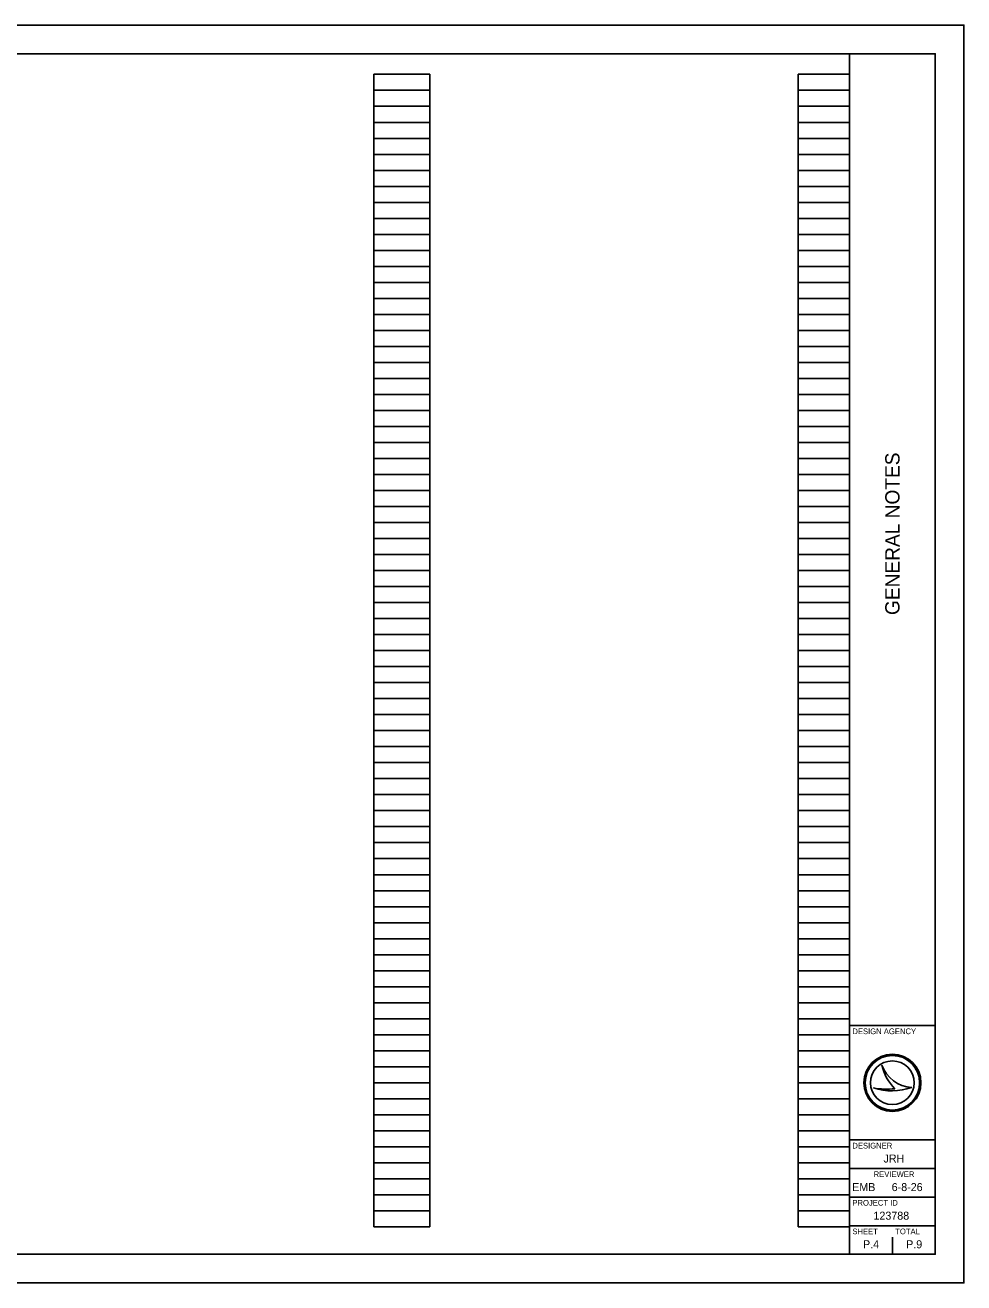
# Model space of a CAD drawing. Extents: x 0 to 34, y 0 to 22.
# Drawn here: x 17.58 to 34, y 0 to 22 of the extents above; entities that cross this region are included whole.
import ezdxf

# ---------------------------------------------------------------- set-up
doc = ezdxf.new("R2010")
doc.units = 0
for name, color, linetype in [('SH_Border', 7, 'Continuous'), ('SH_Cut_Line', 7, 'Continuous'), ('SH_Data', 7, 'Continuous')]:
    doc.layers.add(name, color=color, linetype=linetype)

msp = doc.modelspace()

# ---------------------------------------------------------------- linework, layer by layer
at = {"layer": 'SH_Border'}
for p, q in [((32, 0.5), (32, 21.5)), ((32, 4.5), (33.5, 4.5)), ((32, 2.5), (33.5, 2.5)), ((32, 2), (33.5, 2)), ((32, 1.5), (33.5, 1.5)), ((32, 1), (33.5, 1))]:
    msp.add_line(p, q, dxfattribs=at)
msp.add_lwpolyline([(1.5, 21.5), (33.5, 21.5), (33.5, 0.5), (1.5, 0.5)], close=True, dxfattribs=at)
at = {"layer": 'SH_Cut_Line'}
msp.add_lwpolyline([(0, 0), (34, 0), (34, 22), (0, 22)], close=True, dxfattribs=at)
at = {"layer": 'SH_Data'}
for p, q in [((23.68, 0.98), (23.68, 21.14)), ((23.68, 21.14), (24.66, 21.14)), ((24.66, 0.98), (24.66, 21.14)), ((31.1, 0.98), (31.1, 21.14)), ((31.1, 21.14), (32, 21.14)), ((32, 0.98), (32, 21.14)), ((23.68, 20.86), (24.66, 20.86)), ((31.1, 20.86), (32, 20.86)), ((23.68, 20.58), (24.66, 20.58)), ((31.1, 20.58), (32, 20.58)), ((23.68, 20.3), (24.66, 20.3)), ((31.1, 20.3), (32, 20.3)), ((23.68, 20.02), (24.66, 20.02)), ((31.1, 20.02), (32, 20.02)), ((23.68, 19.74), (24.66, 19.74)), ((31.1, 19.74), (32, 19.74)), ((23.68, 19.46), (24.66, 19.46)), ((31.1, 19.46), (32, 19.46)), ((23.68, 19.18), (24.66, 19.18)), ((31.1, 19.18), (32, 19.18)), ((23.68, 18.9), (24.66, 18.9)), ((31.1, 18.9), (32, 18.9)), ((23.68, 18.62), (24.66, 18.62)), ((31.1, 18.62), (32, 18.62)), ((23.68, 18.34), (24.66, 18.34)), ((31.1, 18.34), (32, 18.34)), ((23.68, 18.06), (24.66, 18.06)), ((31.1, 18.06), (32, 18.06)), ((23.68, 17.78), (24.66, 17.78)), ((31.1, 17.78), (32, 17.78)), ((23.68, 17.5), (24.66, 17.5)), ((31.1, 17.5), (32, 17.5)), ((23.68, 17.22), (24.66, 17.22)), ((31.1, 17.22), (32, 17.22)), ((23.68, 16.94), (24.66, 16.94)), ((31.1, 16.94), (32, 16.94)), ((23.68, 16.66), (24.66, 16.66)), ((31.1, 16.66), (32, 16.66)), ((23.68, 16.38), (24.66, 16.38)), ((31.1, 16.38), (32, 16.38)), ((23.68, 16.1), (24.66, 16.1)), ((31.1, 16.1), (32, 16.1)), ((23.68, 15.82), (24.66, 15.82)), ((31.1, 15.82), (32, 15.82)), ((23.68, 15.54), (24.66, 15.54)), ((31.1, 15.54), (32, 15.54)), ((23.68, 15.26), (24.66, 15.26)), ((31.1, 15.26), (32, 15.26)), ((23.68, 14.98), (24.66, 14.98)), ((31.1, 14.98), (32, 14.98)), ((23.68, 14.7), (24.66, 14.7)), ((31.1, 14.7), (32, 14.7)), ((23.68, 14.42), (24.66, 14.42)), ((31.1, 14.42), (32, 14.42)), ((23.68, 14.14), (24.66, 14.14)), ((31.1, 14.14), (32, 14.14)), ((23.68, 13.86), (24.66, 13.86)), ((31.1, 13.86), (32, 13.86)), ((23.68, 13.58), (24.66, 13.58)), ((31.1, 13.58), (32, 13.58)), ((23.68, 13.3), (24.66, 13.3)), ((31.1, 13.3), (32, 13.3)), ((23.68, 13.02), (24.66, 13.02)), ((31.1, 13.02), (32, 13.02)), ((23.68, 12.74), (24.66, 12.74)), ((31.1, 12.74), (32, 12.74)), ((23.68, 12.46), (24.66, 12.46)), ((31.1, 12.46), (32, 12.46)), ((23.68, 12.18), (24.66, 12.18)), ((31.1, 12.18), (32, 12.18)), ((23.68, 11.9), (24.66, 11.9)), ((31.1, 11.9), (32, 11.9)), ((23.68, 11.62), (24.66, 11.62)), ((31.1, 11.62), (32, 11.62)), ((23.68, 11.34), (24.66, 11.34)), ((31.1, 11.34), (32, 11.34)), ((23.68, 11.06), (24.66, 11.06)), ((31.1, 11.06), (32, 11.06)), ((23.68, 10.78), (24.66, 10.78)), ((31.1, 10.78), (32, 10.78)), ((23.68, 10.5), (24.66, 10.5)), ((31.1, 10.5), (32, 10.5)), ((23.68, 10.22), (24.66, 10.22)), ((31.1, 10.22), (32, 10.22)), ((23.68, 9.94), (24.66, 9.94)), ((31.1, 9.94), (32, 9.94)), ((23.68, 9.66), (24.66, 9.66)), ((31.1, 9.66), (32, 9.66)), ((23.68, 9.38), (24.66, 9.38)), ((31.1, 9.38), (32, 9.38)), ((23.68, 9.1), (24.66, 9.1)), ((31.1, 9.1), (32, 9.1)), ((23.68, 8.82), (24.66, 8.82)), ((31.1, 8.82), (32, 8.82)), ((23.68, 8.54), (24.66, 8.54)), ((31.1, 8.54), (32, 8.54)), ((23.68, 8.26), (24.66, 8.26)), ((31.1, 8.26), (32, 8.26)), ((23.68, 7.98), (24.66, 7.98)), ((31.1, 7.98), (32, 7.98)), ((23.68, 7.7), (24.66, 7.7)), ((31.1, 7.7), (32, 7.7)), ((23.68, 7.42), (24.66, 7.42)), ((31.1, 7.42), (32, 7.42)), ((23.68, 7.14), (24.66, 7.14)), ((31.1, 7.14), (32, 7.14)), ((23.68, 6.86), (24.66, 6.86)), ((31.1, 6.86), (32, 6.86)), ((23.68, 6.58), (24.66, 6.58)), ((31.1, 6.58), (32, 6.58)), ((23.68, 6.3), (24.66, 6.3)), ((31.1, 6.3), (32, 6.3)), ((23.68, 6.02), (24.66, 6.02)), ((31.1, 6.02), (32, 6.02)), ((23.68, 5.74), (24.66, 5.74)), ((31.1, 5.74), (32, 5.74)), ((23.68, 5.46), (24.66, 5.46)), ((31.1, 5.46), (32, 5.46)), ((23.68, 5.18), (24.66, 5.18)), ((31.1, 5.18), (32, 5.18)), ((23.68, 4.9), (24.66, 4.9)), ((31.1, 4.9), (32, 4.9)), ((23.68, 4.62), (24.66, 4.62)), ((31.1, 4.62), (32, 4.62)), ((23.68, 4.34), (24.66, 4.34)), ((31.1, 4.34), (32, 4.34)), ((23.68, 4.06), (24.66, 4.06)), ((31.1, 4.06), (32, 4.06)), ((23.68, 3.78), (24.66, 3.78)), ((31.1, 3.78), (32, 3.78)), ((32.567, 3.81), (32.567, 3.81)), ((23.68, 3.5), (24.66, 3.5)), ((31.1, 3.5), (32, 3.5)), ((32.417, 3.41), (32.417, 3.41)), ((32.75, 3.5), (32.75, 3.5)), ((33.087, 3.419), (33.087, 3.419)), ((23.68, 3.22), (24.66, 3.22)), ((31.1, 3.22), (32, 3.22)), ((23.68, 2.94), (24.66, 2.94)), ((31.1, 2.94), (32, 2.94)), ((23.68, 2.66), (24.66, 2.66)), ((31.1, 2.66), (32, 2.66)), ((23.68, 2.38), (24.66, 2.38)), ((31.1, 2.38), (32, 2.38)), ((23.68, 2.1), (24.66, 2.1)), ((31.1, 2.1), (32, 2.1)), ((23.68, 1.82), (24.66, 1.82)), ((31.1, 1.82), (32, 1.82)), ((23.68, 1.54), (24.66, 1.54)), ((31.1, 1.54), (32, 1.54)), ((23.68, 1.26), (24.66, 1.26)), ((31.1, 1.26), (32, 1.26)), ((23.68, 0.98), (24.66, 0.98)), ((31.1, 0.98), (32, 0.98)), ((32.375, 0.675), (32.375, 0.675)), ((32.75, 0.5), (32.75, 0.8))]:
    msp.add_line(p, q, dxfattribs=at)
for radius in [0.5, 0.477, 0.477, 0.382]:
    msp.add_circle((32.75, 3.5), radius, dxfattribs=at)
for centre, radius, start, end in [((33.116, 3.998), 0.58, 198.9257, 198.9319), ((33.347, 3.97), 0.796, 191.6379, 191.6421), ((33.116, 3.998), 0.58, 198.9319, 267.1657), ((33.347, 3.97), 0.796, 191.6421, 226.0947), ((32.739, 4.37), 1.013, 251.4576, 290.0832), ((32.648, 4.654), 1.266, 259.4964, 259.4995), ((32.739, 4.37), 1.013, 251.4527, 251.4576), ((32.648, 4.654), 1.266, 259.4995, 276.6672)]:
    msp.add_arc(centre, radius, start, end, dxfattribs=at)

# ---------------------------------------------------------------- texts
msp.add_text('GENERAL NOTES', height=0.25, rotation=90, dxfattribs=at).set_placement((32.875, 11.682))
for s, height, p in [('DESIGN AGENCY', 0.1, (32.05, 4.35)), ('DESIGNER', 0.1, (32.05, 2.35)), ('JRH', 0.14, (32.595, 2.105)), ('REVIEWER', 0.1, (32.422, 1.85)), ('EMB', 0.14, (32.047, 1.605)), ('6-8-26', 0.14, (32.738, 1.605)), ('PROJECT ID', 0.1, (32.05, 1.35)), ('123788', 0.14, (32.419, 1.105)), ('SHEET', 0.1, (32.05, 0.85)), ('TOTAL', 0.1, (32.8, 0.85)), ('P.4', 0.14, (32.237, 0.605)), ('P.9', 0.14, (32.99, 0.605))]:
    msp.add_text(s, height=height, dxfattribs=at).set_placement(p)

doc.saveas('drawing.dxf')
